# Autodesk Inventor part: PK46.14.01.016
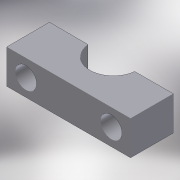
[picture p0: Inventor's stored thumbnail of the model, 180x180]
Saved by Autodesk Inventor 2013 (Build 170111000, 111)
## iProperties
Created: 2005-03
Part Number: PK46.14.01.016
Document SubType Name: Modeling
Designer: elarisa
Manufacturer: Standard
Standards Organization: Custom
Material: Stainless Steel, Austenitic
Density: 8.03 g/cm^3
Author: elarisa
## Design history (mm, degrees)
sketch "Эскиз1"
  geometry: L1 (-33.118, 10.874)-(-33.118, -9.126); L2 (-33.118, -9.126)-(24.882, -9.126); L3 (24.882, -9.126)-(24.882, 10.874); L4 (24.882, 10.874)-(6.837, 10.874); L5 (-15.072, 10.874)-(-33.118, 10.874); A1 r 11 centre (-4.118, 11.874) between (-15.072, 10.874) and (6.837, 10.874)
  constraints: 10 end point, 3 parallel, 2 point on circle, 1 centre point, 1 collinear, 1 perpendicular, 1 vertical
  dimensions: "d0" = 58 distance of L1.end L2.end; "d1" = 29 distance from line of L1 A1.centre; "d2" = 11 radius of A1; "d3" = 1 distance from line of A1.centre L5; "d4" = 20 distance of L1.start L1.end; "d5" = 20 distance of L2.end L3.end (derived)
extrude "Выдавливание1" new body sketch "Эскиз1" distance "d6" = 16; taper "d7" = 0 deg
sketch "Эскиз2"
  geometry: L1 (0, -16)-(18.046, -16) reference; L2 (0, 0)-(0, -16) reference; 2 further points
  dimensions: "d8" = 40 distance of point (49, -8) point (9, -8); "d9" = 8 distance from line of L1 point (9, -8); "d10" = 0 vertical distance of point (49, -8) point (9, -8); "d11" = 9 distance from line of point (9, -8) L2
hole "Отверстие1" sketch "Эскиз2" diameter "d12" = 10; stored, may be unused: countersink angle "d16" = 90 deg, drill point angle "d18" = 118 deg; dims "d13" = 6, "d14" = 4, "d15" = 2, "d17" = 8
body "Solid1"
